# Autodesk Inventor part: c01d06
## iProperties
Created: 2004-05
Part Number: c01d06
Document SubType Name: Modeling
Designer: CADCIM Technologies
Manufacturer: Standard
Standards Organization: Custom
Author: CADCIM Technologies
